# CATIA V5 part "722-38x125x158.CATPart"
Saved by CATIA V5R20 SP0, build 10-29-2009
Part number: 722-38x125x158
Definition: NONE
Nomenclature: 722-38x125x158
Source: Unknown
Description: 722-38x125x158
Bounding box of the stored display mesh (mm): x -19 to 19, y -19 to 19, z -110 to 48
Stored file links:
  C:\Users\Utente\Desktop\IO LAVORO\3D X SITO CF\X SITO\722\722-38x125x158.CATPart

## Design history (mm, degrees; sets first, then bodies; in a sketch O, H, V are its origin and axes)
Body1 "722-38x125x158" (main body)
  Solid1: solid without history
